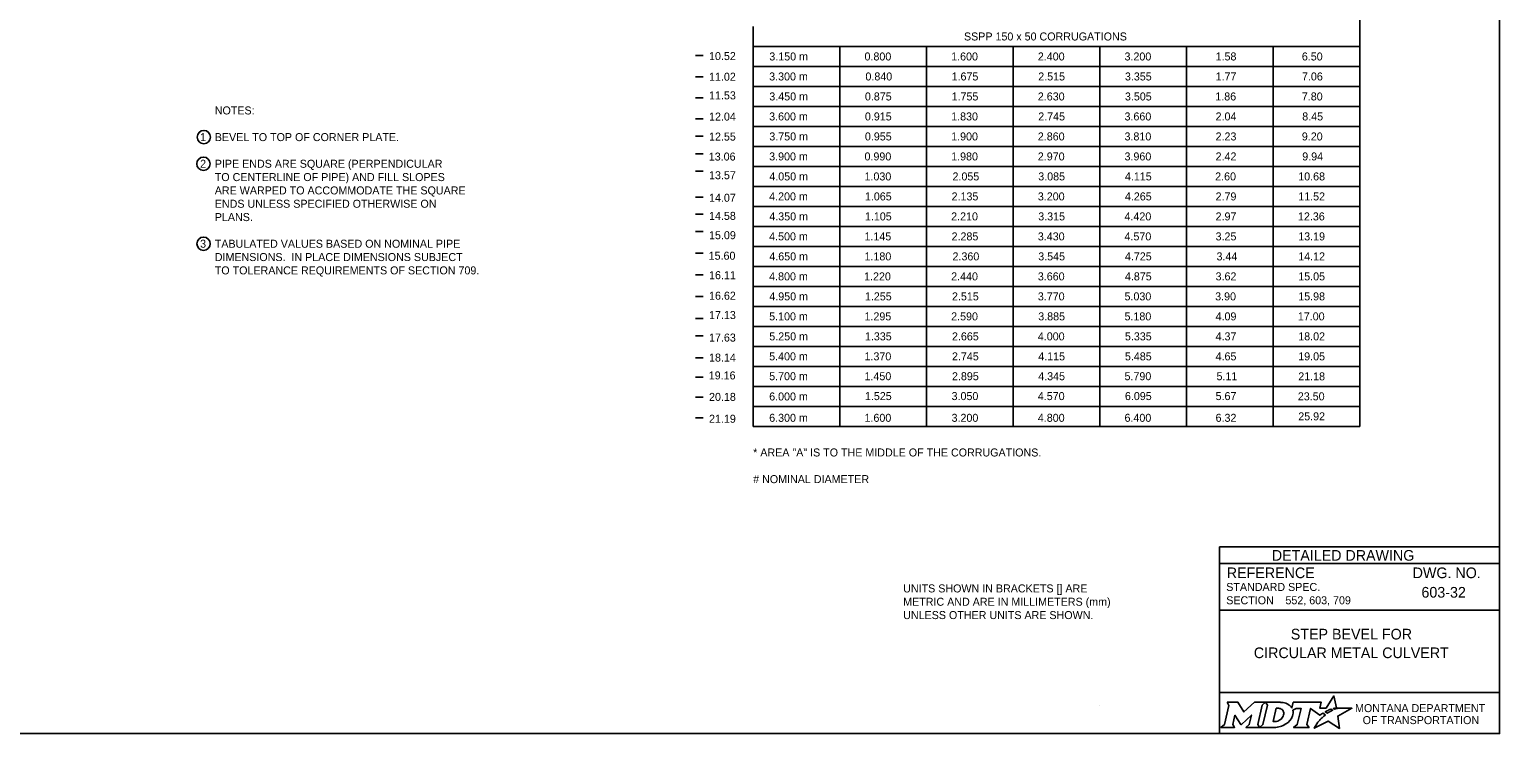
# Model space of a CAD drawing. Extents: x 49957 to 50021, y 49577 to 50011.
# Drawn here: x 50005.72 to 50016.75, y 49987.8 to 49993.08 of the extents above; entities that cross this region are included whole.
import ezdxf

# ---------------------------------------------------------------- set-up
doc = ezdxf.new("R2010")
doc.units = 0
for name, color, linetype in [('Default', 7, 'Continuous'), ('Level 1', 7, 'Continuous'), ('Level 2', 7, 'Continuous'), ('Level 4', 7, 'Continuous'), ('Level 5', 7, 'Continuous')]:
    doc.layers.add(name, color=color, linetype=linetype)

msp = doc.modelspace()

# ---------------------------------------------------------------- linework, layer by layer
at = {"layer": 'Default'}
for points in [[(50014.706, 49988.034), (50014.72, 49988.01), (50014.686, 49987.867), (50014.66, 49987.845), (50014.762, 49987.845), (50014.749, 49987.867), (50014.765, 49987.937), (50014.809, 49987.868), (50014.814, 49987.868), (50014.889, 49987.938), (50014.872, 49987.867), (50014.848, 49987.845), (50014.949, 49987.845), (50014.936, 49987.868), (50014.969, 49988.011)], [(50014.969, 49988.011), (50014.994, 49988.034), (50014.912, 49988.034), (50014.832, 49987.961), (50014.788, 49988.034), (50014.706, 49988.034)], [(50015.108, 49988.034), (50014.994, 49988.034), (50015.009, 49988.011), (50014.975, 49987.867), (50014.949, 49987.845), (50015.06, 49987.845)], [(50015.513, 49987.981), (50015.502, 49987.987), (50015.514, 49987.99), (50015.526, 49987.991), (50015.508, 49988.082), (50015.449, 49987.99), (50015.401, 49987.99), (50015.412, 49988.034), (50015.202, 49988.034), (50015.192, 49987.991), (50015.186, 49988)], [(50015.132, 49987.947), (50015.13, 49987.939), (50015.127, 49987.93), (50015.123, 49987.922), (50015.118, 49987.914), (50015.111, 49987.907), (50015.103, 49987.901), (50015.095, 49987.896), (50015.086, 49987.892), (50015.077, 49987.89), (50015.067, 49987.889), (50015.052, 49987.889), (50015.075, 49987.989), (50015.091, 49987.989), (50015.099, 49987.988), (50015.106, 49987.986), (50015.113, 49987.983), (50015.119, 49987.979), (50015.124, 49987.974), (50015.128, 49987.968), (50015.13, 49987.962), (50015.132, 49987.955), (50015.132, 49987.952), (50015.132, 49987.947)], [(50015.199, 49987.975), (50015.224, 49987.988), (50015.261, 49987.988), (50015.232, 49987.867), (50015.205, 49987.845), (50015.321, 49987.845), (50015.304, 49987.867), (50015.332, 49987.988), (50015.403, 49987.936), (50015.424, 49987.951), (50015.444, 49987.94)], [(50015.388, 49987.884), (50015.373, 49987.86), (50015.368, 49987.852), (50015.362, 49987.844), (50015.36, 49987.839), (50015.465, 49987.893), (50015.549, 49987.838), (50015.536, 49987.93), (50015.643, 49987.989), (50015.594, 49987.989), (50015.564, 49987.99), (50015.543, 49987.99), (50015.536, 49987.989), (50015.531, 49987.987), (50015.523, 49987.985), (50015.513, 49987.981)], [(50015.402, 49987.9), (50015.402, 49987.9)], [(50015.462, 49987.954), (50015.46, 49987.952), (50015.442, 49987.961), (50015.452, 49987.967), (50015.456, 49987.969), (50015.465, 49987.973), (50015.47, 49987.976), (50015.478, 49987.979), (50015.485, 49987.982), (50015.497, 49987.974), (50015.493, 49987.972), (50015.489, 49987.97), (50015.484, 49987.967), (50015.479, 49987.965), (50015.478, 49987.963), (50015.475, 49987.962), (50015.472, 49987.96), (50015.47, 49987.959), (50015.467, 49987.957), (50015.465, 49987.955), (50015.462, 49987.954)], [(50015.106, 49987.852), (50015.114, 49987.855), (50015.127, 49987.86), (50015.148, 49987.871)]]:
    msp.add_lwpolyline(points, dxfattribs=at)
for centre, radius, start, end in [((50015.087, 49987.973), 0.118, 300.9103, 339.1383), ((50015.131, 49987.955), 0.0709, 339.5329, 15.8582)]:
    msp.add_arc(centre, radius, start, end, dxfattribs=at)
for centre, major_axis, ratio, start_param, end_param in [((50015.106, 49987.986), (0.0834, -0.0037), 0.568097, 0.61298, 1.570796), ((50015.161, 49987.994), (0.0361, -0.0295), 0.469099, 1.225588, 1.570796), ((50015.395, 49987.892), (-0.00694, -0.00806), 0.008222, 0, 3.137361), ((50015.412, 49987.911), (-0.0098, -0.0102), 0.016458, 3.141593, 6.279097), ((50015.433, 49987.93), (-0.0112, -0.0097), 0.021651, 3.157348, 6.283185), ((50015.06, 49987.993), (0, 0.148), 0.987302, 3.139398, 3.456847)]:
    msp.add_ellipse(centre, major_axis=major_axis, ratio=ratio, start_param=start_param, end_param=end_param, dxfattribs=at)
at = {"layer": 'Level 1'}
msp.add_lwpolyline([(49999.384, 49998.999), (50016.75, 49998.999), (50016.75, 49987.799), (49999.384, 49987.799)], close=True, dxfattribs=at)
at = {"layer": 'Level 2'}
for p, q in [((50015.702, 49995.654), (50015.702, 49990.104)), ((50011.152, 49993.104), (50011.152, 49990.104)), ((50011.152, 49992.954), (50015.052, 49992.954)), ((50011.802, 49992.954), (50011.802, 49990.104)), ((50012.452, 49992.954), (50012.452, 49990.104)), ((50013.102, 49992.954), (50013.102, 49990.104)), ((50013.752, 49992.954), (50013.752, 49990.104)), ((50014.402, 49992.954), (50014.402, 49990.104)), ((50015.052, 49992.954), (50015.052, 49990.104)), ((50015.052, 49992.954), (50015.702, 49992.954)), ((50011.152, 49992.804), (50015.052, 49992.804)), ((50015.052, 49992.804), (50015.702, 49992.804)), ((50011.152, 49992.654), (50015.052, 49992.654)), ((50015.052, 49992.654), (50015.702, 49992.654)), ((50011.152, 49992.504), (50015.052, 49992.504)), ((50015.052, 49992.504), (50015.702, 49992.504)), ((50011.152, 49992.354), (50015.052, 49992.354)), ((50015.052, 49992.354), (50015.702, 49992.354)), ((50011.152, 49992.204), (50015.052, 49992.204)), ((50015.052, 49992.204), (50015.702, 49992.204)), ((50011.152, 49992.054), (50015.052, 49992.054)), ((50015.052, 49992.054), (50015.702, 49992.054)), ((50011.152, 49991.904), (50015.052, 49991.904)), ((50015.052, 49991.904), (50015.702, 49991.904)), ((50011.152, 49991.754), (50015.052, 49991.754)), ((50015.052, 49991.754), (50015.702, 49991.754)), ((50011.152, 49991.604), (50015.052, 49991.604)), ((50015.052, 49991.604), (50015.702, 49991.604)), ((50011.152, 49991.454), (50015.052, 49991.454)), ((50015.052, 49991.454), (50015.702, 49991.454)), ((50011.152, 49991.304), (50015.052, 49991.304)), ((50015.052, 49991.304), (50015.702, 49991.304)), ((50011.152, 49991.154), (50015.052, 49991.154)), ((50015.052, 49991.154), (50015.702, 49991.154)), ((50011.152, 49991.004), (50015.052, 49991.004)), ((50015.052, 49991.004), (50015.702, 49991.004)), ((50011.152, 49990.854), (50015.052, 49990.854)), ((50015.052, 49990.854), (50015.702, 49990.854)), ((50011.152, 49990.704), (50015.052, 49990.704)), ((50015.052, 49990.704), (50015.702, 49990.704)), ((50011.152, 49990.554), (50015.052, 49990.554)), ((50015.052, 49990.554), (50015.702, 49990.554)), ((50011.152, 49990.404), (50015.052, 49990.404)), ((50015.052, 49990.404), (50015.702, 49990.404)), ((50011.152, 49990.254), (50015.052, 49990.254)), ((50015.052, 49990.254), (50015.702, 49990.254)), ((50011.152, 49990.104), (50015.052, 49990.104)), ((50015.702, 49990.104), (50015.052, 49990.104)), ((50013.746, 49988.012), (50013.746, 49988.012))]:
    msp.add_line(p, q, dxfattribs=at)
for centre in [(50007.032, 49992.274), (50007.029, 49992.074), (50007.03, 49991.474)]:
    msp.add_circle(centre, 0.05, dxfattribs=at)
at = {"layer": 'Level 4'}
for p, q in [((50010.72, 49992.885), (50010.777, 49992.885)), ((50010.72, 49992.727), (50010.777, 49992.727)), ((50010.72, 49992.569), (50010.777, 49992.569)), ((50010.72, 49992.412), (50010.777, 49992.412)), ((50010.72, 49992.28), (50010.777, 49992.28)), ((50010.72, 49992.149), (50010.777, 49992.149)), ((50010.72, 49992.018), (50010.777, 49992.018)), ((50010.72, 49991.823), (50010.777, 49991.823)), ((50010.72, 49991.695), (50010.777, 49991.695)), ((50010.72, 49991.566), (50010.777, 49991.566)), ((50010.72, 49991.403), (50010.777, 49991.403)), ((50010.72, 49991.24), (50010.777, 49991.24)), ((50010.72, 49991.077), (50010.777, 49991.077)), ((50010.72, 49990.913), (50010.777, 49990.913)), ((50010.72, 49990.782), (50010.777, 49990.782)), ((50010.72, 49990.619), (50010.777, 49990.619)), ((50010.72, 49990.473), (50010.777, 49990.473)), ((50010.72, 49990.324), (50010.777, 49990.324)), ((50010.72, 49990.167), (50010.777, 49990.167))]:
    msp.add_line(p, q, dxfattribs=at)
at = {"layer": 'Level 5'}
for p, q in [((50016.75, 49989.199), (50014.65, 49989.199)), ((50014.65, 49989.199), (50014.65, 49987.799)), ((50016.75, 49989.074), (50014.65, 49989.074)), ((50015.144, 49988.799), (50015.144, 49988.799)), ((50016.386, 49988.859), (50016.386, 49988.859)), ((50016.75, 49988.724), (50014.65, 49988.724)), ((50015.7, 49988.475), (50015.7, 49988.475)), ((50016.75, 49988.106), (50014.65, 49988.106))]:
    msp.add_line(p, q, dxfattribs=at)

# ---------------------------------------------------------------- texts
at = {"layer": 'Default'}
for s, p in [('MONTANA DEPARTMENT', (50015.666, 49987.96)), ('OF TRANSPORTATION', (50015.723, 49987.87))]:
    msp.add_text(s, height=0.06, dxfattribs=at).set_placement(p)
at = {"layer": 'Level 2'}
for s, height, p in [('SSPP 150 x 50 CORRUGATIONS', 0.06, (50012.733, 49992.999)), ('3.150 m', 0.06, (50011.273, 49992.849)), ('0.800', 0.06, (50011.987, 49992.849)), ('1.600', 0.06, (50012.637, 49992.849)), ('2.400', 0.06, (50013.287, 49992.849)), ('3.200', 0.06, (50013.937, 49992.849)), ('1.58', 0.06, (50014.62, 49992.849)), ('6.50', 0.06, (50015.267, 49992.849)), ('3.300 m', 0.06, (50011.272, 49992.699)), ('0.840', 0.06, (50011.994, 49992.699)), ('1.675', 0.06, (50012.64, 49992.699)), ('2.515', 0.06, (50013.29, 49992.699)), ('3.355', 0.06, (50013.94, 49992.699)), ('1.77', 0.06, (50014.62, 49992.699)), ('7.06', 0.06, (50015.268, 49992.699)), ('3.450 m', 0.06, (50011.273, 49992.549)), ('0.875', 0.06, (50011.99, 49992.549)), ('1.755', 0.06, (50012.64, 49992.549)), ('2.630', 0.06, (50013.287, 49992.549)), ('3.505', 0.06, (50013.94, 49992.549)), ('1.86', 0.06, (50014.618, 49992.549)), ('7.80', 0.06, (50015.267, 49992.549)), ('NOTES:', 0.06, (50007.114, 49992.444)), ('3.600 m', 0.06, (50011.272, 49992.399)), ('0.915', 0.06, (50011.99, 49992.399)), ('1.830', 0.06, (50012.637, 49992.399)), ('2.745', 0.06, (50013.29, 49992.399)), ('3.660', 0.06, (50013.937, 49992.399)), ('2.04', 0.06, (50014.62, 49992.399)), ('8.45', 0.06, (50015.27, 49992.399)), ('1', 0.06, (50007.004, 49992.244)), ('BEVEL TO TOP OF CORNER PLATE.', 0.06, (50007.114, 49992.244)), ('3.750 m', 0.06, (50011.273, 49992.249)), ('0.955', 0.06, (50011.99, 49992.249)), ('1.900', 0.06, (50012.637, 49992.249)), ('2.860', 0.06, (50013.287, 49992.249)), ('3.810', 0.06, (50013.937, 49992.249)), ('2.23', 0.06, (50014.62, 49992.249)), ('9.20', 0.06, (50015.267, 49992.249)), ('2', 0.06, (50007.004, 49992.044)), ('PIPE ENDS ARE SQUARE (PERPENDICULAR', 0.06, (50007.114, 49992.044)), ('3.900 m', 0.06, (50011.272, 49992.099)), ('0.990', 0.06, (50011.987, 49992.099)), ('1.980', 0.06, (50012.637, 49992.099)), ('2.970', 0.06, (50013.287, 49992.099)), ('3.960', 0.06, (50013.937, 49992.099)), ('2.42', 0.06, (50014.62, 49992.099)), ('9.94', 0.06, (50015.27, 49992.099)), ('TO CENTERLINE OF PIPE) AND FILL SLOPES', 0.06, (50007.114, 49991.944)), ('4.050 m', 0.06, (50011.273, 49991.949)), ('1.030', 0.06, (50011.987, 49991.949)), ('2.055', 0.06, (50012.647, 49991.949)), ('3.085', 0.06, (50013.29, 49991.949)), ('4.115', 0.06, (50013.94, 49991.949)), ('2.60', 0.06, (50014.617, 49991.949)), ('10.68', 0.06, (50015.24, 49991.949)), ('ARE WARPED TO ACCOMMODATE THE SQUARE', 0.06, (50007.114, 49991.844)), ('4.200 m', 0.06, (50011.272, 49991.799)), ('1.065', 0.06, (50011.99, 49991.799)), ('2.135', 0.06, (50012.64, 49991.799)), ('3.200', 0.06, (50013.287, 49991.799)), ('4.265', 0.06, (50013.94, 49991.799)), ('2.79', 0.06, (50014.62, 49991.799)), ('11.52', 0.06, (50015.24, 49991.799)), ('ENDS UNLESS SPECIFIED OTHERWISE ON', 0.06, (50007.114, 49991.744)), ('PLANS.', 0.06, (50007.114, 49991.644)), ('4.350 m', 0.06, (50011.273, 49991.649)), ('1.105', 0.06, (50011.99, 49991.649)), ('2.210', 0.06, (50012.637, 49991.649)), ('3.315', 0.06, (50013.29, 49991.649)), ('4.420', 0.06, (50013.937, 49991.649)), ('2.97', 0.06, (50014.62, 49991.649)), ('12.36', 0.06, (50015.238, 49991.649)), ('4.500 m', 0.06, (50011.272, 49991.499)), ('1.145', 0.06, (50011.987, 49991.499)), ('2.285', 0.06, (50012.64, 49991.499)), ('3.430', 0.06, (50013.287, 49991.499)), ('4.570', 0.06, (50013.937, 49991.499)), ('3.25', 0.06, (50014.62, 49991.499)), ('13.19', 0.06, (50015.24, 49991.499)), ('3', 0.06, (50007.004, 49991.444)), ('TABULATED VALUES BASED ON NOMINAL PIPE', 0.06, (50007.114, 49991.444)), ('DIMENSIONS.  IN PLACE DIMENSIONS SUBJECT', 0.06, (50007.114, 49991.344)), ('4.650 m', 0.06, (50011.273, 49991.349)), ('1.180', 0.06, (50011.987, 49991.349)), ('2.360', 0.06, (50012.647, 49991.349)), ('3.545', 0.06, (50013.29, 49991.349)), ('4.725', 0.06, (50013.94, 49991.349)), ('3.44', 0.06, (50014.627, 49991.349)), ('14.12', 0.06, (50015.24, 49991.349)), ('TO TOLERANCE REQUIREMENTS OF SECTION 709.', 0.06, (50007.114, 49991.244)), ('4.800 m', 0.06, (50011.272, 49991.199)), ('1.220', 0.06, (50011.984, 49991.199)), ('2.440', 0.06, (50012.637, 49991.199)), ('3.660', 0.06, (50013.287, 49991.199)), ('4.875', 0.06, (50013.94, 49991.199)), ('3.62', 0.06, (50014.62, 49991.199)), ('15.05', 0.06, (50015.24, 49991.199)), ('4.950 m', 0.06, (50011.273, 49991.049)), ('1.255', 0.06, (50011.99, 49991.049)), ('2.515', 0.06, (50012.643, 49991.049)), ('3.770', 0.06, (50013.287, 49991.049)), ('5.030', 0.06, (50013.937, 49991.049)), ('3.90', 0.06, (50014.617, 49991.049)), ('15.98', 0.06, (50015.24, 49991.049)), ('5.100 m', 0.06, (50011.272, 49990.899)), ('1.295', 0.06, (50011.987, 49990.899)), ('2.590', 0.06, (50012.637, 49990.899)), ('3.885', 0.06, (50013.29, 49990.899)), ('5.180', 0.06, (50013.937, 49990.899)), ('4.09', 0.06, (50014.62, 49990.899)), ('17.00', 0.06, (50015.237, 49990.899)), ('5.250 m', 0.06, (50011.273, 49990.749)), ('1.335', 0.06, (50011.99, 49990.749)), ('2.665', 0.06, (50012.643, 49990.749)), ('4.000', 0.06, (50013.287, 49990.749)), ('5.335', 0.06, (50013.94, 49990.749)), ('4.37', 0.06, (50014.62, 49990.749)), ('18.02', 0.06, (50015.24, 49990.749)), ('5.400 m', 0.06, (50011.272, 49990.599)), ('1.370', 0.06, (50011.987, 49990.599)), ('2.745', 0.06, (50012.643, 49990.599)), ('4.115', 0.06, (50013.29, 49990.599)), ('5.485', 0.06, (50013.94, 49990.599)), ('4.65', 0.06, (50014.62, 49990.599)), ('19.05', 0.06, (50015.24, 49990.599)), ('5.700 m', 0.06, (50011.272, 49990.45)), ('1.450', 0.06, (50011.987, 49990.45)), ('2.895', 0.06, (50012.643, 49990.45)), ('4.345', 0.06, (50013.29, 49990.45)), ('5.790', 0.06, (50013.937, 49990.45)), ('5.11', 0.06, (50014.627, 49990.45)), ('21.18', 0.06, (50015.24, 49990.449)), ('6.000 m', 0.06, (50011.272, 49990.298)), ('1.525', 0.06, (50011.99, 49990.301)), ('3.050', 0.06, (50012.64, 49990.301)), ('4.570', 0.06, (50013.287, 49990.301)), ('6.095', 0.06, (50013.94, 49990.301)), ('5.67', 0.06, (50014.62, 49990.301)), ('23.50', 0.06, (50015.237, 49990.299)), ('25.92', 0.06, (50015.24, 49990.149)), ('6.300 m', 0.06, (50011.272, 49990.138)), ('1.600', 0.06, (50011.987, 49990.138)), ('3.200', 0.06, (50012.64, 49990.138)), ('4.800', 0.06, (50013.287, 49990.138)), ('6.400', 0.06, (50013.937, 49990.138)), ('6.32', 0.06, (50014.62, 49990.138)), ('* AREA "A" IS TO THE MIDDLE OF THE CORRUGATIONS.', 0.06, (50011.152, 49989.878)), ('# NOMINAL DIAMETER', 0.06, (50011.152, 49989.678)), ('UNITS SHOWN IN BRACKETS [] ARE ', 0.06, (50012.277, 49988.858)), ('603-32', 0.08, (50016.164, 49988.819)), ('METRIC AND ARE IN MILLIMETERS (mm) ', 0.06, (50012.277, 49988.758)), ('552, 603, 709', 0.06, (50015.144, 49988.769)), ('UNLESS OTHER UNITS ARE SHOWN.', 0.06, (50012.277, 49988.658)), ('STEP BEVEL FOR', 0.08, (50015.184, 49988.505)), ('CIRCULAR METAL CULVERT', 0.08, (50014.907, 49988.365))]:
    msp.add_text(s, height=height, dxfattribs=at).set_placement(p)
at = {"layer": 'Level 4'}
for s, p in [('10.52', (50010.821, 49992.852)), ('11.02', (50010.821, 49992.697)), ('11.53', (50010.821, 49992.557)), ('12.04', (50010.821, 49992.398)), ('12.55', (50010.821, 49992.248)), ('13.06', (50010.819, 49992.098)), ('13.57', (50010.821, 49991.958)), ('14.07', (50010.821, 49991.789)), ('14.58', (50010.821, 49991.653)), ('15.09', (50010.821, 49991.508)), ('15.60', (50010.818, 49991.354)), ('16.11', (50010.821, 49991.208)), ('16.62', (50010.821, 49991.054)), ('17.13', (50010.821, 49990.909)), ('17.63', (50010.821, 49990.74)), ('18.14', (50010.821, 49990.59)), ('19.16', (50010.819, 49990.456)), ('20.18', (50010.821, 49990.295)), ('21.19', (50010.821, 49990.131))]:
    msp.add_text(s, height=0.06, dxfattribs=at).set_placement(p)
at = {"layer": 'Level 5'}
for s, height, p in [('DETAILED DRAWING', 0.0799, (50015.042, 49989.096)), ('REFERENCE', 0.08, (50014.704, 49988.965)), ('DWG. NO.', 0.08, (50016.098, 49988.965)), ('STANDARD SPEC.', 0.06, (50014.7, 49988.869)), ('SECTION', 0.06, (50014.7, 49988.769))]:
    msp.add_text(s, height=height, dxfattribs=at).set_placement(p)

doc.saveas('drawing.dxf')
